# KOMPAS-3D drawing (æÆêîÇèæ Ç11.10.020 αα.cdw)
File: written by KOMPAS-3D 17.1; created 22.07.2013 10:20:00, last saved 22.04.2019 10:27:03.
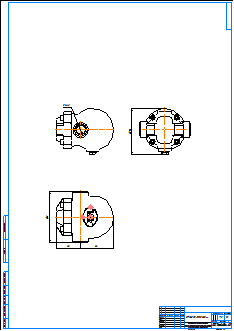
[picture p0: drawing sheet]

Sheet 1: A1, portrait

Title block, sheet 1: name: СТИМАКС А11.10.020 рр; material: Внимание! Данный продукт является объектом авторского права ООО «Торговый Дом АДЛ». / Запрещается изменение, копирование, распространение / (в том числе путем копирования на другие сайты и ресурсы в Интернете) / или любое иное использование информации и объектов без предварительного / согласия правообладателя (ООО «Торговый Дом АДЛ»).; mass: 7,5; sheets: 1; organisation: ООО "Торговый дом АДЛ"; sheet format: A1; stored path: \\adlc.lan\data\АДЛ_ПКД\3D-модели\ADL production\Конденсатоотводчики СТИМАКС\Поплавковые\Серия А11\KOMPAS 2D\СТИМАКС А11.10.020 рр.cdw

Views: Вид 1, Проекционный вид 2
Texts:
  Klimkovich
  ADL
Dimensions and other numbers on the sheet: 130; 62; 84; 1:1; 1; 7,5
